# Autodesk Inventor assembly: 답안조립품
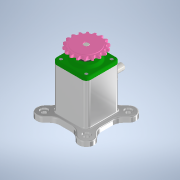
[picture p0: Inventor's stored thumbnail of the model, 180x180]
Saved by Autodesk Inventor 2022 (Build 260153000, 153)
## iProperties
Created: 2022-05
Part Number: 답안조립품
Document SubType Name: Assembly
Designer: admin
Author: admin
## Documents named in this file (11)
- C:\Users\admin\Desktop\720509V1012\답안조립품.iam
- C:\Users\admin\Desktop\720509V1012\본체.ipt
- C:\Users\admin\Desktop\720509V1012\720509V1012\커버.ipt
- C:\Users\admin\Desktop\720509V1012\720509V1012\베어링 6203.ipt
- C:\Users\admin\Desktop\720509V1012\720509V1012\편심축.ipt
- C:\Users\admin\Desktop\720509V1012\720509V1012\오일 실.ipt
- C:\Users\admin\Desktop\720509V1012\720509V1012\부시.ipt
- C:\Users\admin\Desktop\720509V1012\720509V1012\슬라이더.ipt
- C:\Users\admin\Desktop\720509V1012\720509V1012\키 4 x 4 x 14.ipt
- C:\Users\admin\Desktop\720509V1012\720509V1012\스프로킷.ipt
- C:\Users\admin\Desktop\720509V1012\720509V1012\볼트 M4.ipt
